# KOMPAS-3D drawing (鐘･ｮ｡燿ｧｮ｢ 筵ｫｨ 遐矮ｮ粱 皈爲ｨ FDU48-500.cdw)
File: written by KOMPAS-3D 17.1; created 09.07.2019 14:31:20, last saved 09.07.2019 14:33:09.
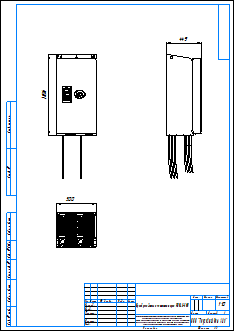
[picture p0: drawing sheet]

Sheet 1: A3, portrait

Title block, sheet 1: name: Преобразователи частоты серии FDU48-500; sheets: 1; sheet format: A3; stored path: \\adlc.lan\data\АДЛ_ПКД\3D-модели\Поставщики\Оборудование Emotron\Преобразователи частоты\Серия FDU 2.0\KOMPAS 2D\Преобразователи частоты серии FDU48-500.cdw

Views: Вид 1
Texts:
  user
  CONTINUOUS_RGB_0_0_0_THICK_0.18
  POLYLINE_STYLE_0.18_RGB_0_0_0
  Рама для чертежей
  Лит-Масса-Масштаб
  Материал-Предприятие
  Масштаб
  Изм.
  Лист
  № докум.
  Подп.
  Дата
  Лит.
  Разраб.
  Пров.
  Т.контр.
  Листов
  Внимание! Данный продукт является объектом авторского права ООО «Торговый Дом АДЛ».
  Запрещается изменение, копирование, распространение
  (в том числе путем копирования на другие сайты и ресурсы в Интернете)
  или любое иное использование информации и объектов без предварительного
  согласия правообладателя (ООО «Торговый Дом АДЛ»).
  Н.контр.
  Утв.
  ООО "Торговый дом АДЛ"
  Изменение
  Номер документа
  Подпись
  Обозначение документа
  Наименование изделия
  Масса изделия по ГОСТ 2.109-73
  Порядковый номер листа
  Общее количество листов в документе
  Характер работы, выполненной лицом, подписавшим документ
  Наименование или индекс предприятия, выпускающего документ
  Инв. № подл.
  Подп. и дата
  Взам. инв. №
  Инв. № дубл.
  Инвентарный номер подлинника по ГОСТ 2.501-68
  Подпись принявшего подлинник в отдел технической документации
  Инвентарный номер подлинника, взамен которого выпущен данный подлинник
  Инвентарный номер дубликата по ГОСТ 2.502-68
  Подпись принявшего дубликат в отдел технической документации
  Справ. №
  Перв. примен.
  Обозначение документа, взамен или на основании которого выпущен данный документ
  Обозначение документа, в котором впервые записан данный документ
  Подпись лица, копировавшего чертеж
  Обозначение формата листа
  !Рама для чертежа
Dimensions and other numbers on the sheet: 500; 1036; 449; 1:10; 1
